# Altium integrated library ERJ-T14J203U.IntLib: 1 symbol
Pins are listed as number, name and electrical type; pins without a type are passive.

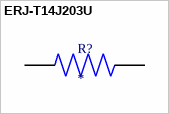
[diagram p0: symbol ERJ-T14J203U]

## ERJ-T14J203U
designator R?
Anti-Pulse Chip Resistor 1210 5%, 20Kohm , 7 Ree; MP: ERJ-T14J203U
footprint RESC3225X70N
pins: 1, 2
